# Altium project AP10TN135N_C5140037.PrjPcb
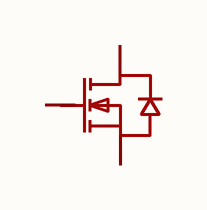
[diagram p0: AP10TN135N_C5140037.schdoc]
1 sheet, 1 parts. Net scope: global (net labels, ports and power ports of the same name join across sheets).

## Sheet AP10TN135N_C5140037.schdoc
size 127 x 101 mm

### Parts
Q?  ap10tn135n_c5140037  [SOT-23-3_L2.9-W1.3-P1.90-LS2.4-BR]  (value not drawn)

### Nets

Not connected (* = marked no-connect by the designer): Q? 1(G) 2(S) 3(D)

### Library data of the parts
Q? = ap10tn135n_c5140037: 数量:1个N沟道;漏源电压(Vdss):100V;连续漏极电流(Id):5A;导通电阻(RDS(on)):90mΩ@10V；120mΩ@4.5V;耗散功率(Pd):2.5W;阈值电压(Vgs(th)):1.5V;; Manufacturer: MSKSEMI(美森科); AddInBom: yes; ModelId: c62791f0466c4ae2a892c056b845b0ca; ModelName: SOT-23-3P_L2.9-W1.3-H1.0-LS2.4-P0.95; ModelTransform: 98.425,114.173,0,180,0,0,0.0005,-0.0005,0; Number: 1个N沟道; Drain to Source Voltage: 100V; Current - Continuous Drain(Id): 5A; Pd - Power Dissipation: 2.5W; Gate Threshold Voltage (Vgs(th)): 1.5V; Gate Charge(Qg): 18nC@10V; Input Capacitance(Ciss): 765pF; Reverse Transfer Capacitance (Crss@Vds): 33pF; Type: N沟道; Output Capacitance(Coss): 38pF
